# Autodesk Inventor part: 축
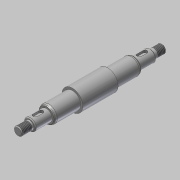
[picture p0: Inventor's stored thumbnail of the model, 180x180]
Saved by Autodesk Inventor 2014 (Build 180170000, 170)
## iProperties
Created: 2020-05
Part Number: 축
Material: 강철, 연강
Document SubType Name: Modeling
Designer: mduedu
Density: 1 g/cm^3
Appearance: Steel
Author: mduedu
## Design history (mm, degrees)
sketch "스케치1"
  geometry: L1 (0, 0)-(21, 0); L2 (21, 0)-(21, 12.5); L3 (21, 12.5)-(0, 12.5); L4 (0, 12.5)-(0, 0); L5 (21, 0)-(52, 0); L6 (52, 0)-(52, 10); L7 (52, 10)-(21, 10); L8 (21, 10)-(21, 0); L9 (52, 0)-(72, 0); L10 (72, 0)-(72, 7); L11 (72, 7)-(52, 7); L12 (52, 7)-(52, 0); L13 (72, 0)-(86, 0); L14 (86, 0)-(86, 5); L15 (86, 5)-(72, 5); L16 (72, 5)-(72, 0); L17 (0, 0)-(-21, 0); L18 (-21, 0)-(-21, 12.5); L19 (-21, 12.5)-(0, 12.5); L20 (-21, 0)-(-52, 0); L21 (-52, 0)-(-52, 10); L22 (-52, 10)-(-21, 10); L23 (-21, 10)-(-21, 0); L24 (-52, 0)-(-72, 0); L25 (-72, 0)-(-72, 7); L26 (-72, 7)-(-52, 7); L27 (-52, 7)-(-52, 0); L28 (-72, 0)-(-86, 0); L29 (-86, 0)-(-86, 5); L30 (-86, 5)-(-72, 5); L31 (-72, 5)-(-72, 0)
  constraints: 62 end point, 11 symmetric about line, 8 parallel, 4 horizontal, 4 perpendicular
  dimensions: "d0" = 172 distance between parallel lines of L14 L29; "d2" = 25 diameter of L3 L1; "d3" = 20 diameter of L7 L5; "d4" = 14 diameter of L11 L9; "d5" = 10 diameter of L15 L13; "d6" = 42 distance of L2.end L18.end; "d7" = 31 distance of L6.end L7.end; "d8" = 20 distance of L10.end L11.end; "d9" = 14 distance of L14.end L15.end (derived)
revolve "회전1" sketch "스케치1" stored, may be unused: angle "d10" = 90 deg
sketch "스케치2"
  geometry: L1 (72, -5)-(72, -7) reference; L2 (72, -7)-(52, -7) reference; L3 (52, -7)-(52, -10) reference; L4 (52, -10)-(21, -10) reference; L5 (21, -10)-(21, -12.5) reference; L6 (21, -12.5)-(-21, -12.5) reference; L7 (-21, -12.5)-(-21, -10) reference; L8 (-21, -10)-(-52, -10) reference; L9 (-52, -10)-(-52, -7) reference; L10 (-52, -7)-(-72, -7) reference; L11 (-72, -7)-(-72, -5) reference; L12 (-72, -5)-(-86, -5) reference; L13 (-86, -5)-(-86, 5) reference; L14 (-86, 5)-(-72, 5) reference; L15 (-72, 5)-(-72, 7) reference; L16 (-72, 7)-(-52, 7) reference; L17 (-52, 7)-(-52, 10) reference; L18 (-52, 10)-(-21, 10) reference; L19 (-21, 10)-(-21, 12.5) reference; L20 (-21, 12.5)-(21, 12.5) reference; L21 (21, 12.5)-(21, 10) reference; L22 (21, 10)-(52, 10) reference; L23 (52, 10)-(52, 7) reference; L24 (52, 7)-(72, 7) reference; L25 (72, 7)-(72, 5) reference; L26 (72, 5)-(86, 5) reference; L27 (86, 5)-(86, -5) reference; L28 (86, -5)-(72, -5) reference; L29 (-86, 0)-(86, 0); L30 (0, -12.5)-(0, 12.5); L31 (-52, 8.85)-(-50.008, 10); L32 (-50.008, 10)-(-52, 10); L33 (-52, 10)-(-52, 8.85); 1 further point
  constraints: 10 end point, 4 midpoint, 2 collinear, 2 point on line
  dimensions: "d11" = 17.7 diameter of L31.start L29; "d12" = 30 deg angle of L31 L32
revolve "회전2" sketch "스케치2" stored, may be unused: angle "d13" = 90 deg
fillet "모깎기1" dims "d14" = 4, "d15" = 0.5
node "작업 평면1"
sketch "스케치3"
  geometry: L1 (-6, 2.5)-(6, 2.5); L2 (6, 2.5)-(6, -2.5); L3 (6, -2.5)-(-6, -2.5); L4 (-6, -2.5)-(-6, 2.5); L5 (-10, 8.561)-(-10, -8.561) reference; 2 further points
  constraints: 8 end point, 2 parallel, 1 horizontal, 1 horizontal alignment, 1 midpoint, 1 perpendicular
  dimensions: "d16" = 5 distance of L1.end L2.end; "d18" = 4 distance between parallel lines of L4 L5; "d19" = 12 distance of L1.start L1.end
extrude "돌출1" cut sketch "스케치3" distance "d20" = 3; taper "d21" = 0 deg
fillet "모깎기2" dims "d22" = 2.5
fillet "모깎기3" dims "d23" = 2.5
feature "스레드1" dims "d24" = 12, "d25" = 0
feature "스레드2" dims "d26" = 10, "d27" = 0
chamfer "모따기1" distance "d28" = 1; stored, may be unused: second distance "d29" = 2, angle "d30" = 45 deg
chamfer "모따기2" distance "d31" = 1; stored, may be unused: second distance "d32" = 2, angle "d33" = 45 deg
node "솔리드1"
mirror "대칭1"
mirror "대칭2"
node "절단 모서리 투영1"
